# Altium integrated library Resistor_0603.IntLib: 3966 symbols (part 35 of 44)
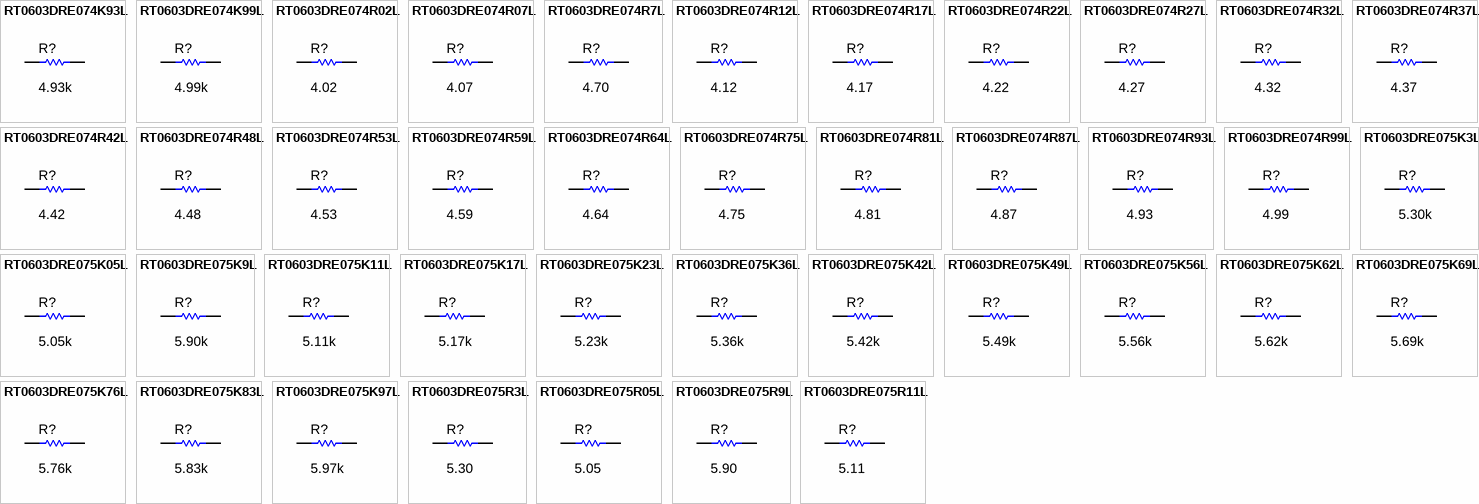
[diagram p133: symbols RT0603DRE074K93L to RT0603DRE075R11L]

## RT0603DRE075K23L
designator R?  ValueDisplayed: 5.23k  (hidden comment: RT0603DRE075K23L)
RES, 5.23 k, 0.5%, 0.1 W, 0603; Manufacturer: Yageo America; CompType: Resistor; Value: 5.23k; Res_ohm: 5230; Value_Code: 5k23; Tolerance_%: 0.5; Power_W: 0.1; Value2: 0.1W; VDC_V: 75; TempCo: 50 ppm/C; SizeArea_mm2: 1.28; SizeX_mm: 1.6; SizeY_mm: 0.8; SizeZ_mm: 1; EIA_Code: E192; U/M: EA; AEC Category: Q200; Green_Lifecycle: Active; Green_REACh: Passed
signal-integrity model Resistor
simulation model Resistor
footprint 0603
footprint 0603M
footprint 0603L
footprint 0603_HV
footprint 0603S
pins: 1, 2

## RT0603DRE075K36L
designator R?  ValueDisplayed: 5.36k  (hidden comment: RT0603DRE075K36L)
RES, 5.36 k, 0.5%, 0.1 W, 0603; Manufacturer: Yageo America; CompType: Resistor; Value: 5.36k; Res_ohm: 5360; Value_Code: 5k36; Tolerance_%: 0.5; Power_W: 0.1; Value2: 0.1W; VDC_V: 75; TempCo: 50 ppm/C; SizeArea_mm2: 1.28; SizeX_mm: 1.6; SizeY_mm: 0.8; SizeZ_mm: 1; EIA_Code: E192; U/M: EA; AEC Category: Q200
signal-integrity model Resistor
simulation model Resistor
footprint 0603
footprint 0603M
footprint 0603L
footprint 0603_HV
footprint 0603S
pins: 1, 2

## RT0603DRE075K42L
designator R?  ValueDisplayed: 5.42k  (hidden comment: RT0603DRE075K42L)
RES, 5.42 k, 0.5%, 0.1 W, 0603; Manufacturer: Yageo America; CompType: Resistor; Value: 5.42k; Res_ohm: 5420; Value_Code: 5k42; Tolerance_%: 0.5; Power_W: 0.1; Value2: 0.1W; VDC_V: 75; TempCo: 50 ppm/C; SizeArea_mm2: 1.28; SizeX_mm: 1.6; SizeY_mm: 0.8; SizeZ_mm: 1; EIA_Code: E192; U/M: EA; AEC Category: Q200
signal-integrity model Resistor
simulation model Resistor
footprint 0603
footprint 0603M
footprint 0603L
footprint 0603_HV
footprint 0603S
pins: 1, 2

## RT0603DRE075K49L
designator R?  ValueDisplayed: 5.49k  (hidden comment: RT0603DRE075K49L)
RES, 5.49 k, 0.5%, 0.1 W, 0603; Manufacturer: Yageo America; CompType: Resistor; Value: 5.49k; Res_ohm: 5490; Value_Code: 5k49; Tolerance_%: 0.5; Power_W: 0.1; Value2: 0.1W; VDC_V: 75; TempCo: 50 ppm/C; SizeArea_mm2: 1.28; SizeX_mm: 1.6; SizeY_mm: 0.8; SizeZ_mm: 1; EIA_Code: E192; U/M: EA; AEC Category: Q200
signal-integrity model Resistor
simulation model Resistor
footprint 0603
footprint 0603M
footprint 0603L
footprint 0603_HV
footprint 0603S
pins: 1, 2

## RT0603DRE075K56L
designator R?  ValueDisplayed: 5.56k  (hidden comment: RT0603DRE075K56L)
RES, 5.56 k, 0.5%, 0.1 W, 0603; Manufacturer: Yageo America; CompType: Resistor; Value: 5.56k; Res_ohm: 5560; Value_Code: 5k56; Tolerance_%: 0.5; Power_W: 0.1; Value2: 0.1W; VDC_V: 75; TempCo: 50 ppm/C; SizeArea_mm2: 1.28; SizeX_mm: 1.6; SizeY_mm: 0.8; SizeZ_mm: 1; EIA_Code: E192; U/M: EA; AEC Category: Q200
signal-integrity model Resistor
simulation model Resistor
footprint 0603
footprint 0603M
footprint 0603L
footprint 0603_HV
footprint 0603S
pins: 1, 2

## RT0603DRE075K62L
designator R?  ValueDisplayed: 5.62k  (hidden comment: RT0603DRE075K62L)
RES, 5.62 k, 0.5%, 0.1 W, 0603; Manufacturer: Yageo America; CompType: Resistor; Value: 5.62k; Res_ohm: 5620; Value_Code: 5k62; Tolerance_%: 0.5; Power_W: 0.1; Value2: 0.1W; VDC_V: 75; TempCo: 50 ppm/C; SizeArea_mm2: 1.28; SizeX_mm: 1.6; SizeY_mm: 0.8; SizeZ_mm: 1; EIA_Code: E192; U/M: EA; AEC Category: Q200
signal-integrity model Resistor
simulation model Resistor
footprint 0603
footprint 0603M
footprint 0603L
footprint 0603_HV
footprint 0603S
pins: 1, 2

## RT0603DRE075K69L
designator R?  ValueDisplayed: 5.69k  (hidden comment: RT0603DRE075K69L)
RES, 5.69 k, 0.5%, 0.1 W, 0603; Manufacturer: Yageo America; CompType: Resistor; Value: 5.69k; Res_ohm: 5690; Value_Code: 5k69; Tolerance_%: 0.5; Power_W: 0.1; Value2: 0.1W; VDC_V: 75; TempCo: 50 ppm/C; SizeArea_mm2: 1.28; SizeX_mm: 1.6; SizeY_mm: 0.8; SizeZ_mm: 1; EIA_Code: E192; U/M: EA; AEC Category: Q200
signal-integrity model Resistor
simulation model Resistor
footprint 0603
footprint 0603M
footprint 0603L
footprint 0603_HV
footprint 0603S
pins: 1, 2

## RT0603DRE075K76L
designator R?  ValueDisplayed: 5.76k  (hidden comment: RT0603DRE075K76L)
RES, 5.76 k, 0.5%, 0.1 W, 0603; Manufacturer: Yageo America; CompType: Resistor; Value: 5.76k; Res_ohm: 5760; Value_Code: 5k76; Tolerance_%: 0.5; Power_W: 0.1; Value2: 0.1W; VDC_V: 75; TempCo: 50 ppm/C; SizeArea_mm2: 1.28; SizeX_mm: 1.6; SizeY_mm: 0.8; SizeZ_mm: 1; EIA_Code: E192; U/M: EA; AEC Category: Q200
signal-integrity model Resistor
simulation model Resistor
footprint 0603
footprint 0603M
footprint 0603L
footprint 0603_HV
footprint 0603S
pins: 1, 2

## RT0603DRE075K83L
designator R?  ValueDisplayed: 5.83k  (hidden comment: RT0603DRE075K83L)
RES, 5.83 k, 0.5%, 0.1 W, 0603; Manufacturer: Yageo America; CompType: Resistor; Value: 5.83k; Res_ohm: 5830; Value_Code: 5k83; Tolerance_%: 0.5; Power_W: 0.1; Value2: 0.1W; VDC_V: 75; TempCo: 50 ppm/C; SizeArea_mm2: 1.28; SizeX_mm: 1.6; SizeY_mm: 0.8; SizeZ_mm: 1; EIA_Code: E192; U/M: EA; AEC Category: Q200
signal-integrity model Resistor
simulation model Resistor
footprint 0603
footprint 0603M
footprint 0603L
footprint 0603_HV
footprint 0603S
pins: 1, 2

## RT0603DRE075K97L
designator R?  ValueDisplayed: 5.97k  (hidden comment: RT0603DRE075K97L)
RES, 5.97 k, 0.5%, 0.1 W, 0603; Manufacturer: Yageo America; CompType: Resistor; Value: 5.97k; Res_ohm: 5970; Value_Code: 5k97; Tolerance_%: 0.5; Power_W: 0.1; Value2: 0.1W; VDC_V: 75; TempCo: 50 ppm/C; SizeArea_mm2: 1.28; SizeX_mm: 1.6; SizeY_mm: 0.8; SizeZ_mm: 1; EIA_Code: E192; U/M: EA; AEC Category: Q200
signal-integrity model Resistor
simulation model Resistor
footprint 0603
footprint 0603M
footprint 0603L
footprint 0603_HV
footprint 0603S
pins: 1, 2

## RT0603DRE075R3L
designator R?  ValueDisplayed: 5.30  (hidden comment: RT0603DRE075R3L)
RES, 5.30, 0.5%, 0.1 W, 0603; Manufacturer: Yageo America; CompType: Resistor; Value: 5.30; Res_ohm: 5.3; Value_Code: 5R30; Tolerance_%: 0.5; Power_W: 0.1; Value2: 0.1W; VDC_V: 75; TempCo: 50 ppm/C; SizeArea_mm2: 1.28; SizeX_mm: 1.6; SizeY_mm: 0.8; SizeZ_mm: 1; EIA_Code: E192; U/M: EA; AEC Category: Q200
signal-integrity model Resistor
simulation model Resistor
footprint 0603
footprint 0603M
footprint 0603L
footprint 0603_HV
footprint 0603S
pins: 1, 2

## RT0603DRE075R05L
designator R?  ValueDisplayed: 5.05  (hidden comment: RT0603DRE075R05L)
RES, 5.05, 0.5%, 0.1 W, 0603; Manufacturer: Yageo America; CompType: Resistor; Value: 5.05; Value_Code: 5R05; Tolerance_%: 0.5; Power_W: 0.1; Value2: 0.1W; VDC_V: 75; TempCo: 50 ppm/C; SizeArea_mm2: 1.28; SizeX_mm: 1.6; SizeY_mm: 0.8; SizeZ_mm: 1; EIA_Code: E192; U/M: EA; AEC Category: Q200
signal-integrity model Resistor
simulation model Resistor
footprint 0603
footprint 0603M
footprint 0603L
footprint 0603_HV
footprint 0603S
pins: 1, 2

## RT0603DRE075R9L
designator R?  ValueDisplayed: 5.90  (hidden comment: RT0603DRE075R9L)
RES, 5.90, 0.5%, 0.1 W, 0603; Manufacturer: Yageo America; CompType: Resistor; Value: 5.90; Res_ohm: 5.9; Value_Code: 5R90; Tolerance_%: 0.5; Power_W: 0.1; Value2: 0.1W; VDC_V: 75; TempCo: 50 ppm/C; SizeArea_mm2: 1.28; SizeX_mm: 1.6; SizeY_mm: 0.8; SizeZ_mm: 1; EIA_Code: E192; U/M: EA; AEC Category: Q200
signal-integrity model Resistor
simulation model Resistor
footprint 0603
footprint 0603M
footprint 0603L
footprint 0603_HV
footprint 0603S
pins: 1, 2

## RT0603DRE075R11L
designator R?  ValueDisplayed: 5.11  (hidden comment: RT0603DRE075R11L)
RES, 5.11, 0.5%, 0.1 W, 0603; Manufacturer: Yageo America; CompType: Resistor; Value: 5.11; Value_Code: 5R11; Tolerance_%: 0.5; Power_W: 0.1; Value2: 0.1W; VDC_V: 75; TempCo: 50 ppm/C; SizeArea_mm2: 1.28; SizeX_mm: 1.6; SizeY_mm: 0.8; SizeZ_mm: 1; EIA_Code: E192; U/M: EA; AEC Category: Q200
signal-integrity model Resistor
simulation model Resistor
footprint 0603
footprint 0603M
footprint 0603L
footprint 0603_HV
footprint 0603S
pins: 1, 2

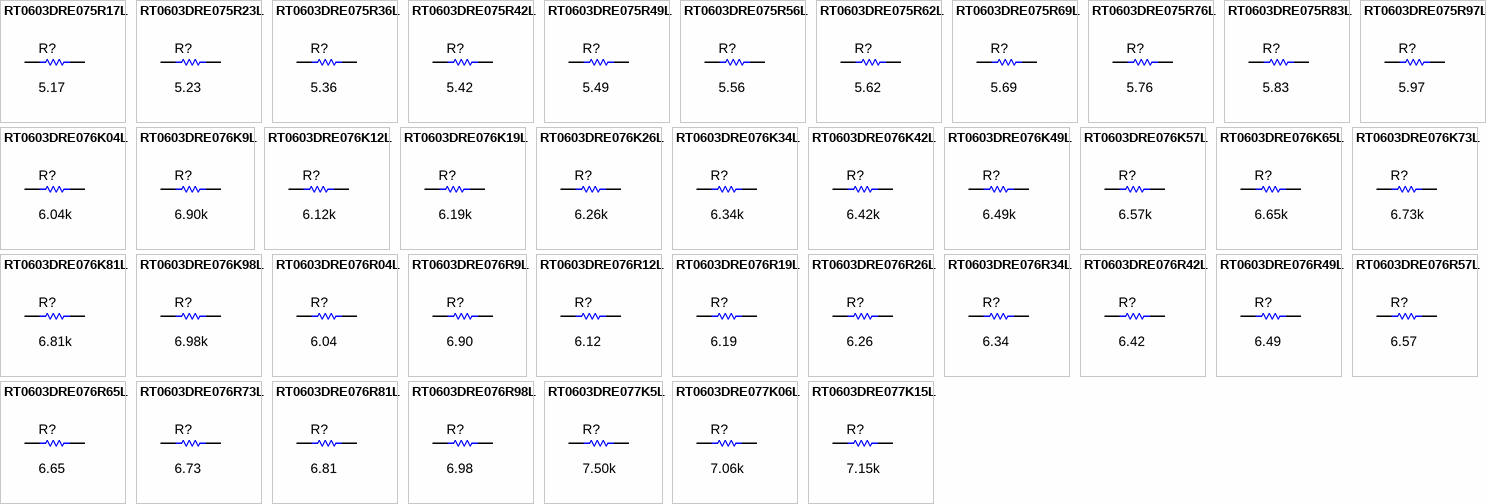
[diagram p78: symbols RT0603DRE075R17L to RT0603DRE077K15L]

## RT0603DRE075R17L
designator R?  ValueDisplayed: 5.17  (hidden comment: RT0603DRE075R17L)
RES, 5.17, 0.5%, 0.1 W, 0603; Manufacturer: Yageo America; CompType: Resistor; Value: 5.17; Value_Code: 5R17; Tolerance_%: 0.5; Power_W: 0.1; Value2: 0.1W; VDC_V: 75; TempCo: 50 ppm/C; SizeArea_mm2: 1.28; SizeX_mm: 1.6; SizeY_mm: 0.8; SizeZ_mm: 1; EIA_Code: E192; U/M: EA; AEC Category: Q200
signal-integrity model Resistor
simulation model Resistor
footprint 0603
footprint 0603M
footprint 0603L
footprint 0603_HV
footprint 0603S
pins: 1, 2

## RT0603DRE075R23L
designator R?  ValueDisplayed: 5.23  (hidden comment: RT0603DRE075R23L)
RES, 5.23, 0.5%, 0.1 W, 0603; Manufacturer: Yageo America; CompType: Resistor; Value: 5.23; Value_Code: 5R23; Tolerance_%: 0.5; Power_W: 0.1; Value2: 0.1W; VDC_V: 75; TempCo: 50 ppm/C; SizeArea_mm2: 1.28; SizeX_mm: 1.6; SizeY_mm: 0.8; SizeZ_mm: 1; EIA_Code: E192; U/M: EA; AEC Category: Q200
signal-integrity model Resistor
simulation model Resistor
footprint 0603
footprint 0603M
footprint 0603L
footprint 0603_HV
footprint 0603S
pins: 1, 2

## RT0603DRE075R36L
designator R?  ValueDisplayed: 5.36  (hidden comment: RT0603DRE075R36L)
RES, 5.36, 0.5%, 0.1 W, 0603; Manufacturer: Yageo America; CompType: Resistor; Value: 5.36; Value_Code: 5R36; Tolerance_%: 0.5; Power_W: 0.1; Value2: 0.1W; VDC_V: 75; TempCo: 50 ppm/C; SizeArea_mm2: 1.28; SizeX_mm: 1.6; SizeY_mm: 0.8; SizeZ_mm: 1; EIA_Code: E192; U/M: EA; AEC Category: Q200
signal-integrity model Resistor
simulation model Resistor
footprint 0603
footprint 0603M
footprint 0603L
footprint 0603_HV
footprint 0603S
pins: 1, 2

## RT0603DRE075R42L
designator R?  ValueDisplayed: 5.42  (hidden comment: RT0603DRE075R42L)
RES, 5.42, 0.5%, 0.1 W, 0603; Manufacturer: Yageo America; CompType: Resistor; Value: 5.42; Value_Code: 5R42; Tolerance_%: 0.5; Power_W: 0.1; Value2: 0.1W; VDC_V: 75; TempCo: 50 ppm/C; SizeArea_mm2: 1.28; SizeX_mm: 1.6; SizeY_mm: 0.8; SizeZ_mm: 1; EIA_Code: E192; U/M: EA; AEC Category: Q200
signal-integrity model Resistor
simulation model Resistor
footprint 0603
footprint 0603M
footprint 0603L
footprint 0603_HV
footprint 0603S
pins: 1, 2

## RT0603DRE075R49L
designator R?  ValueDisplayed: 5.49  (hidden comment: RT0603DRE075R49L)
RES, 5.49, 0.5%, 0.1 W, 0603; Manufacturer: Yageo America; CompType: Resistor; Value: 5.49; Value_Code: 5R49; Tolerance_%: 0.5; Power_W: 0.1; Value2: 0.1W; VDC_V: 75; TempCo: 50 ppm/C; SizeArea_mm2: 1.28; SizeX_mm: 1.6; SizeY_mm: 0.8; SizeZ_mm: 1; EIA_Code: E192; U/M: EA; AEC Category: Q200
signal-integrity model Resistor
simulation model Resistor
footprint 0603
footprint 0603M
footprint 0603L
footprint 0603_HV
footprint 0603S
pins: 1, 2

## RT0603DRE075R56L
designator R?  ValueDisplayed: 5.56  (hidden comment: RT0603DRE075R56L)
RES, 5.56, 0.5%, 0.1 W, 0603; Manufacturer: Yageo America; CompType: Resistor; Value: 5.56; Value_Code: 5R56; Tolerance_%: 0.5; Power_W: 0.1; Value2: 0.1W; VDC_V: 75; TempCo: 50 ppm/C; SizeArea_mm2: 1.28; SizeX_mm: 1.6; SizeY_mm: 0.8; SizeZ_mm: 1; EIA_Code: E192; U/M: EA; AEC Category: Q200
signal-integrity model Resistor
simulation model Resistor
footprint 0603
footprint 0603M
footprint 0603L
footprint 0603_HV
footprint 0603S
pins: 1, 2

## RT0603DRE075R62L
designator R?  ValueDisplayed: 5.62  (hidden comment: RT0603DRE075R62L)
RES, 5.62, 0.5%, 0.1 W, 0603; Manufacturer: Yageo America; CompType: Resistor; Value: 5.62; Value_Code: 5R62; Tolerance_%: 0.5; Power_W: 0.1; Value2: 0.1W; VDC_V: 75; TempCo: 50 ppm/C; SizeArea_mm2: 1.28; SizeX_mm: 1.6; SizeY_mm: 0.8; SizeZ_mm: 1; EIA_Code: E192; U/M: EA; AEC Category: Q200
signal-integrity model Resistor
simulation model Resistor
footprint 0603
footprint 0603M
footprint 0603L
footprint 0603_HV
footprint 0603S
pins: 1, 2

## RT0603DRE075R69L
designator R?  ValueDisplayed: 5.69  (hidden comment: RT0603DRE075R69L)
RES, 5.69, 0.5%, 0.1 W, 0603; Manufacturer: Yageo America; CompType: Resistor; Value: 5.69; Value_Code: 5R69; Tolerance_%: 0.5; Power_W: 0.1; Value2: 0.1W; VDC_V: 75; TempCo: 50 ppm/C; SizeArea_mm2: 1.28; SizeX_mm: 1.6; SizeY_mm: 0.8; SizeZ_mm: 1; EIA_Code: E192; U/M: EA; AEC Category: Q200
signal-integrity model Resistor
simulation model Resistor
footprint 0603
footprint 0603M
footprint 0603L
footprint 0603_HV
footprint 0603S
pins: 1, 2

## RT0603DRE075R76L
designator R?  ValueDisplayed: 5.76  (hidden comment: RT0603DRE075R76L)
RES, 5.76, 0.5%, 0.1 W, 0603; Manufacturer: Yageo America; CompType: Resistor; Value: 5.76; Value_Code: 5R76; Tolerance_%: 0.5; Power_W: 0.1; Value2: 0.1W; VDC_V: 75; TempCo: 50 ppm/C; SizeArea_mm2: 1.28; SizeX_mm: 1.6; SizeY_mm: 0.8; SizeZ_mm: 1; EIA_Code: E192; U/M: EA; AEC Category: Q200
signal-integrity model Resistor
simulation model Resistor
footprint 0603
footprint 0603M
footprint 0603L
footprint 0603_HV
footprint 0603S
pins: 1, 2

## RT0603DRE075R83L
designator R?  ValueDisplayed: 5.83  (hidden comment: RT0603DRE075R83L)
RES, 5.83, 0.5%, 0.1 W, 0603; Manufacturer: Yageo America; CompType: Resistor; Value: 5.83; Value_Code: 5R83; Tolerance_%: 0.5; Power_W: 0.1; Value2: 0.1W; VDC_V: 75; TempCo: 50 ppm/C; SizeArea_mm2: 1.28; SizeX_mm: 1.6; SizeY_mm: 0.8; SizeZ_mm: 1; EIA_Code: E192; U/M: EA; AEC Category: Q200
signal-integrity model Resistor
simulation model Resistor
footprint 0603
footprint 0603M
footprint 0603L
footprint 0603_HV
footprint 0603S
pins: 1, 2

## RT0603DRE075R97L
designator R?  ValueDisplayed: 5.97  (hidden comment: RT0603DRE075R97L)
RES, 5.97, 0.5%, 0.1 W, 0603; Manufacturer: Yageo America; CompType: Resistor; Value: 5.97; Value_Code: 5R97; Tolerance_%: 0.5; Power_W: 0.1; Value2: 0.1W; VDC_V: 75; TempCo: 50 ppm/C; SizeArea_mm2: 1.28; SizeX_mm: 1.6; SizeY_mm: 0.8; SizeZ_mm: 1; EIA_Code: E192; U/M: EA; AEC Category: Q200
signal-integrity model Resistor
simulation model Resistor
footprint 0603
footprint 0603M
footprint 0603L
footprint 0603_HV
footprint 0603S
pins: 1, 2

## RT0603DRE076K04L
designator R?  ValueDisplayed: 6.04k  (hidden comment: RT0603DRE076K04L)
RES, 6.04 k, 0.5%, 0.1 W, 0603; Manufacturer: Yageo America; CompType: Resistor; Value: 6.04k; Res_ohm: 6040; Value_Code: 6k04; Tolerance_%: 0.5; Power_W: 0.1; Value2: 0.1W; VDC_V: 75; TempCo: 50 ppm/C; SizeArea_mm2: 1.28; SizeX_mm: 1.6; SizeY_mm: 0.8; SizeZ_mm: 1; EIA_Code: E192; U/M: EA; AEC Category: Q200
signal-integrity model Resistor
simulation model Resistor
footprint 0603
footprint 0603M
footprint 0603L
footprint 0603_HV
footprint 0603S
pins: 1, 2

## RT0603DRE076K9L
designator R?  ValueDisplayed: 6.90k  (hidden comment: RT0603DRE076K9L)
RES, 6.90 k, 0.5%, 0.1 W, 0603; Manufacturer: Yageo America; CompType: Resistor; Value: 6.90k; Res_ohm: 6900; Value_Code: 6k90; Tolerance_%: 0.5; Power_W: 0.1; Value2: 0.1W; VDC_V: 75; TempCo: 50 ppm/C; SizeArea_mm2: 1.28; SizeX_mm: 1.6; SizeY_mm: 0.8; SizeZ_mm: 1; EIA_Code: E192; U/M: EA; AEC Category: Q200
signal-integrity model Resistor
simulation model Resistor
footprint 0603
footprint 0603M
footprint 0603L
footprint 0603_HV
footprint 0603S
pins: 1, 2

## RT0603DRE076K12L
designator R?  ValueDisplayed: 6.12k  (hidden comment: RT0603DRE076K12L)
RES, 6.12 k, 0.5%, 0.1 W, 0603; Manufacturer: Yageo America; CompType: Resistor; Value: 6.12k; Res_ohm: 6120; Value_Code: 6k12; Tolerance_%: 0.5; Power_W: 0.1; Value2: 0.1W; VDC_V: 75; TempCo: 50 ppm/C; SizeArea_mm2: 1.28; SizeX_mm: 1.6; SizeY_mm: 0.8; SizeZ_mm: 1; EIA_Code: E192; U/M: EA; AEC Category: Q200
signal-integrity model Resistor
simulation model Resistor
footprint 0603
footprint 0603M
footprint 0603L
footprint 0603_HV
footprint 0603S
pins: 1, 2

## RT0603DRE076K19L
designator R?  ValueDisplayed: 6.19k  (hidden comment: RT0603DRE076K19L)
RES, 6.19 k, 0.5%, 0.1 W, 0603; Manufacturer: Yageo America; CompType: Resistor; Value: 6.19k; Res_ohm: 6190; Value_Code: 6k19; Tolerance_%: 0.5; Power_W: 0.1; Value2: 0.1W; VDC_V: 75; TempCo: 50 ppm/C; SizeArea_mm2: 1.28; SizeX_mm: 1.6; SizeY_mm: 0.8; SizeZ_mm: 1; EIA_Code: E192; U/M: EA; AEC Category: Q200
signal-integrity model Resistor
simulation model Resistor
footprint 0603
footprint 0603M
footprint 0603L
footprint 0603_HV
footprint 0603S
pins: 1, 2

## RT0603DRE076K26L
designator R?  ValueDisplayed: 6.26k  (hidden comment: RT0603DRE076K26L)
RES, 6.26 k, 0.5%, 0.1 W, 0603; Manufacturer: Yageo America; CompType: Resistor; Value: 6.26k; Res_ohm: 6260; Value_Code: 6k26; Tolerance_%: 0.5; Power_W: 0.1; Value2: 0.1W; VDC_V: 75; TempCo: 50 ppm/C; SizeArea_mm2: 1.28; SizeX_mm: 1.6; SizeY_mm: 0.8; SizeZ_mm: 1; EIA_Code: E192; U/M: EA; AEC Category: Q200
signal-integrity model Resistor
simulation model Resistor
footprint 0603
footprint 0603M
footprint 0603L
footprint 0603_HV
footprint 0603S
pins: 1, 2

## RT0603DRE076K34L
designator R?  ValueDisplayed: 6.34k  (hidden comment: RT0603DRE076K34L)
RES, 6.34 k, 0.5%, 0.1 W, 0603; Manufacturer: Yageo America; CompType: Resistor; Value: 6.34k; Res_ohm: 6340; Value_Code: 6k34; Tolerance_%: 0.5; Power_W: 0.1; Value2: 0.1W; VDC_V: 75; TempCo: 50 ppm/C; SizeArea_mm2: 1.28; SizeX_mm: 1.6; SizeY_mm: 0.8; SizeZ_mm: 1; EIA_Code: E192; U/M: EA; AEC Category: Q200
signal-integrity model Resistor
simulation model Resistor
footprint 0603
footprint 0603M
footprint 0603L
footprint 0603_HV
footprint 0603S
pins: 1, 2

## RT0603DRE076K42L
designator R?  ValueDisplayed: 6.42k  (hidden comment: RT0603DRE076K42L)
RES, 6.42 k, 0.5%, 0.1 W, 0603; Manufacturer: Yageo America; CompType: Resistor; Value: 6.42k; Res_ohm: 6420; Value_Code: 6k42; Tolerance_%: 0.5; Power_W: 0.1; Value2: 0.1W; VDC_V: 75; TempCo: 50 ppm/C; SizeArea_mm2: 1.28; SizeX_mm: 1.6; SizeY_mm: 0.8; SizeZ_mm: 1; EIA_Code: E192; U/M: EA; AEC Category: Q200
signal-integrity model Resistor
simulation model Resistor
footprint 0603
footprint 0603M
footprint 0603L
footprint 0603_HV
footprint 0603S
pins: 1, 2

## RT0603DRE076K49L
designator R?  ValueDisplayed: 6.49k  (hidden comment: RT0603DRE076K49L)
RES, 6.49 k, 0.5%, 0.1 W, 0603; Manufacturer: Yageo America; CompType: Resistor; Value: 6.49k; Res_ohm: 6490; Value_Code: 6k49; Tolerance_%: 0.5; Power_W: 0.1; Value2: 0.1W; VDC_V: 75; TempCo: 50 ppm/C; SizeArea_mm2: 1.28; SizeX_mm: 1.6; SizeY_mm: 0.8; SizeZ_mm: 1; EIA_Code: E192; U/M: EA; AEC Category: Q200
signal-integrity model Resistor
simulation model Resistor
footprint 0603
footprint 0603M
footprint 0603L
footprint 0603_HV
footprint 0603S
pins: 1, 2

## RT0603DRE076K57L
designator R?  ValueDisplayed: 6.57k  (hidden comment: RT0603DRE076K57L)
RES, 6.57 k, 0.5%, 0.1 W, 0603; Manufacturer: Yageo America; CompType: Resistor; Value: 6.57k; Res_ohm: 6570; Value_Code: 6k57; Tolerance_%: 0.5; Power_W: 0.1; Value2: 0.1W; VDC_V: 75; TempCo: 50 ppm/C; SizeArea_mm2: 1.28; SizeX_mm: 1.6; SizeY_mm: 0.8; SizeZ_mm: 1; EIA_Code: E192; U/M: EA; AEC Category: Q200
signal-integrity model Resistor
simulation model Resistor
footprint 0603
footprint 0603M
footprint 0603L
footprint 0603_HV
footprint 0603S
pins: 1, 2

## RT0603DRE076K65L
designator R?  ValueDisplayed: 6.65k  (hidden comment: RT0603DRE076K65L)
RES, 6.65 k, 0.5%, 0.1 W, 0603; Manufacturer: Yageo America; CompType: Resistor; Value: 6.65k; Res_ohm: 6650; Value_Code: 6k65; Tolerance_%: 0.5; Power_W: 0.1; Value2: 0.1W; VDC_V: 75; TempCo: 50 ppm/C; SizeArea_mm2: 1.28; SizeX_mm: 1.6; SizeY_mm: 0.8; SizeZ_mm: 1; EIA_Code: E192; U/M: EA; AEC Category: Q200
signal-integrity model Resistor
simulation model Resistor
footprint 0603
footprint 0603M
footprint 0603L
footprint 0603_HV
footprint 0603S
pins: 1, 2

## RT0603DRE076K73L
designator R?  ValueDisplayed: 6.73k  (hidden comment: RT0603DRE076K73L)
RES, 6.73 k, 0.5%, 0.1 W, 0603; Manufacturer: Yageo America; CompType: Resistor; Value: 6.73k; Res_ohm: 6730; Value_Code: 6k73; Tolerance_%: 0.5; Power_W: 0.1; Value2: 0.1W; VDC_V: 75; TempCo: 50 ppm/C; SizeArea_mm2: 1.28; SizeX_mm: 1.6; SizeY_mm: 0.8; SizeZ_mm: 1; EIA_Code: E192; U/M: EA; AEC Category: Q200
signal-integrity model Resistor
simulation model Resistor
footprint 0603
footprint 0603M
footprint 0603L
footprint 0603_HV
footprint 0603S
pins: 1, 2

## RT0603DRE076K81L
designator R?  ValueDisplayed: 6.81k  (hidden comment: RT0603DRE076K81L)
RES, 6.81 k, 0.5%, 0.1 W, 0603; Manufacturer: Yageo America; CompType: Resistor; Value: 6.81k; Res_ohm: 6810; Value_Code: 6k81; Tolerance_%: 0.5; Power_W: 0.1; Value2: 0.1W; VDC_V: 75; TempCo: 50 ppm/C; SizeArea_mm2: 1.28; SizeX_mm: 1.6; SizeY_mm: 0.8; SizeZ_mm: 1; EIA_Code: E192; U/M: EA; AEC Category: Q200
signal-integrity model Resistor
simulation model Resistor
footprint 0603
footprint 0603M
footprint 0603L
footprint 0603_HV
footprint 0603S
pins: 1, 2

## RT0603DRE076K98L
designator R?  ValueDisplayed: 6.98k  (hidden comment: RT0603DRE076K98L)
RES, 6.98 k, 0.5%, 0.1 W, 0603; Manufacturer: Yageo America; CompType: Resistor; Value: 6.98k; Res_ohm: 6980; Value_Code: 6k98; Tolerance_%: 0.5; Power_W: 0.1; Value2: 0.1W; VDC_V: 75; TempCo: 50 ppm/C; SizeArea_mm2: 1.28; SizeX_mm: 1.6; SizeY_mm: 0.8; SizeZ_mm: 1; EIA_Code: E192; U/M: EA; AEC Category: Q200
signal-integrity model Resistor
simulation model Resistor
footprint 0603
footprint 0603M
footprint 0603L
footprint 0603_HV
footprint 0603S
pins: 1, 2

## RT0603DRE076R04L
designator R?  ValueDisplayed: 6.04  (hidden comment: RT0603DRE076R04L)
RES, 6.04, 0.5%, 0.1 W, 0603; Manufacturer: Yageo America; CompType: Resistor; Value: 6.04; Value_Code: 6R04; Tolerance_%: 0.5; Power_W: 0.1; Value2: 0.1W; VDC_V: 75; TempCo: 50 ppm/C; SizeArea_mm2: 1.28; SizeX_mm: 1.6; SizeY_mm: 0.8; SizeZ_mm: 1; EIA_Code: E192; U/M: EA; AEC Category: Q200
signal-integrity model Resistor
simulation model Resistor
footprint 0603
footprint 0603M
footprint 0603L
footprint 0603_HV
footprint 0603S
pins: 1, 2

## RT0603DRE076R9L
designator R?  ValueDisplayed: 6.90  (hidden comment: RT0603DRE076R9L)
RES, 6.90, 0.5%, 0.1 W, 0603; Manufacturer: Yageo America; CompType: Resistor; Value: 6.90; Res_ohm: 6.9; Value_Code: 6R90; Tolerance_%: 0.5; Power_W: 0.1; Value2: 0.1W; VDC_V: 75; TempCo: 50 ppm/C; SizeArea_mm2: 1.28; SizeX_mm: 1.6; SizeY_mm: 0.8; SizeZ_mm: 1; EIA_Code: E192; U/M: EA; AEC Category: Q200
signal-integrity model Resistor
simulation model Resistor
footprint 0603
footprint 0603M
footprint 0603L
footprint 0603_HV
footprint 0603S
pins: 1, 2

## RT0603DRE076R12L
designator R?  ValueDisplayed: 6.12  (hidden comment: RT0603DRE076R12L)
RES, 6.12, 0.5%, 0.1 W, 0603; Manufacturer: Yageo America; CompType: Resistor; Value: 6.12; Value_Code: 6R12; Tolerance_%: 0.5; Power_W: 0.1; Value2: 0.1W; VDC_V: 75; TempCo: 50 ppm/C; SizeArea_mm2: 1.28; SizeX_mm: 1.6; SizeY_mm: 0.8; SizeZ_mm: 1; EIA_Code: E192; U/M: EA; AEC Category: Q200
signal-integrity model Resistor
simulation model Resistor
footprint 0603
footprint 0603M
footprint 0603L
footprint 0603_HV
footprint 0603S
pins: 1, 2

## RT0603DRE076R19L
designator R?  ValueDisplayed: 6.19  (hidden comment: RT0603DRE076R19L)
RES, 6.19, 0.5%, 0.1 W, 0603; Manufacturer: Yageo America; CompType: Resistor; Value: 6.19; Value_Code: 6R19; Tolerance_%: 0.5; Power_W: 0.1; Value2: 0.1W; VDC_V: 75; TempCo: 50 ppm/C; SizeArea_mm2: 1.28; SizeX_mm: 1.6; SizeY_mm: 0.8; SizeZ_mm: 1; EIA_Code: E192; U/M: EA; AEC Category: Q200
signal-integrity model Resistor
simulation model Resistor
footprint 0603
footprint 0603M
footprint 0603L
footprint 0603_HV
footprint 0603S
pins: 1, 2

## RT0603DRE076R26L
designator R?  ValueDisplayed: 6.26  (hidden comment: RT0603DRE076R26L)
RES, 6.26, 0.5%, 0.1 W, 0603; Manufacturer: Yageo America; CompType: Resistor; Value: 6.26; Value_Code: 6R26; Tolerance_%: 0.5; Power_W: 0.1; Value2: 0.1W; VDC_V: 75; TempCo: 50 ppm/C; SizeArea_mm2: 1.28; SizeX_mm: 1.6; SizeY_mm: 0.8; SizeZ_mm: 1; EIA_Code: E192; U/M: EA; AEC Category: Q200
signal-integrity model Resistor
simulation model Resistor
footprint 0603
footprint 0603M
footprint 0603L
footprint 0603_HV
footprint 0603S
pins: 1, 2

## RT0603DRE076R34L
designator R?  ValueDisplayed: 6.34  (hidden comment: RT0603DRE076R34L)
RES, 6.34, 0.5%, 0.1 W, 0603; Manufacturer: Yageo America; CompType: Resistor; Value: 6.34; Value_Code: 6R34; Tolerance_%: 0.5; Power_W: 0.1; Value2: 0.1W; VDC_V: 75; TempCo: 50 ppm/C; SizeArea_mm2: 1.28; SizeX_mm: 1.6; SizeY_mm: 0.8; SizeZ_mm: 1; EIA_Code: E192; U/M: EA; AEC Category: Q200
signal-integrity model Resistor
simulation model Resistor
footprint 0603
footprint 0603M
footprint 0603L
footprint 0603_HV
footprint 0603S
pins: 1, 2

## RT0603DRE076R42L
designator R?  ValueDisplayed: 6.42  (hidden comment: RT0603DRE076R42L)
RES, 6.42, 0.5%, 0.1 W, 0603; Manufacturer: Yageo America; CompType: Resistor; Value: 6.42; Value_Code: 6R42; Tolerance_%: 0.5; Power_W: 0.1; Value2: 0.1W; VDC_V: 75; TempCo: 50 ppm/C; SizeArea_mm2: 1.28; SizeX_mm: 1.6; SizeY_mm: 0.8; SizeZ_mm: 1; EIA_Code: E192; U/M: EA; AEC Category: Q200
signal-integrity model Resistor
simulation model Resistor
footprint 0603
footprint 0603M
footprint 0603L
footprint 0603_HV
footprint 0603S
pins: 1, 2

## RT0603DRE076R49L
designator R?  ValueDisplayed: 6.49  (hidden comment: RT0603DRE076R49L)
RES, 6.49, 0.5%, 0.1 W, 0603; Manufacturer: Yageo America; CompType: Resistor; Value: 6.49; Value_Code: 6R49; Tolerance_%: 0.5; Power_W: 0.1; Value2: 0.1W; VDC_V: 75; TempCo: 50 ppm/C; SizeArea_mm2: 1.28; SizeX_mm: 1.6; SizeY_mm: 0.8; SizeZ_mm: 1; EIA_Code: E192; U/M: EA; AEC Category: Q200
signal-integrity model Resistor
simulation model Resistor
footprint 0603
footprint 0603M
footprint 0603L
footprint 0603_HV
footprint 0603S
pins: 1, 2

## RT0603DRE076R57L
designator R?  ValueDisplayed: 6.57  (hidden comment: RT0603DRE076R57L)
RES, 6.57, 0.5%, 0.1 W, 0603; Manufacturer: Yageo America; CompType: Resistor; Value: 6.57; Value_Code: 6R57; Tolerance_%: 0.5; Power_W: 0.1; Value2: 0.1W; VDC_V: 75; TempCo: 50 ppm/C; SizeArea_mm2: 1.28; SizeX_mm: 1.6; SizeY_mm: 0.8; SizeZ_mm: 1; EIA_Code: E192; U/M: EA; AEC Category: Q200
signal-integrity model Resistor
simulation model Resistor
footprint 0603
footprint 0603M
footprint 0603L
footprint 0603_HV
footprint 0603S
pins: 1, 2

## RT0603DRE076R65L
designator R?  ValueDisplayed: 6.65  (hidden comment: RT0603DRE076R65L)
RES, 6.65, 0.5%, 0.1 W, 0603; Manufacturer: Yageo America; CompType: Resistor; Value: 6.65; Value_Code: 6R65; Tolerance_%: 0.5; Power_W: 0.1; Value2: 0.1W; VDC_V: 75; TempCo: 50 ppm/C; SizeArea_mm2: 1.28; SizeX_mm: 1.6; SizeY_mm: 0.8; SizeZ_mm: 1; EIA_Code: E192; U/M: EA; AEC Category: Q200
signal-integrity model Resistor
simulation model Resistor
footprint 0603
footprint 0603M
footprint 0603L
footprint 0603_HV
footprint 0603S
pins: 1, 2

## RT0603DRE076R73L
designator R?  ValueDisplayed: 6.73  (hidden comment: RT0603DRE076R73L)
RES, 6.73, 0.5%, 0.1 W, 0603; Manufacturer: Yageo America; CompType: Resistor; Value: 6.73; Value_Code: 6R73; Tolerance_%: 0.5; Power_W: 0.1; Value2: 0.1W; VDC_V: 75; TempCo: 50 ppm/C; SizeArea_mm2: 1.28; SizeX_mm: 1.6; SizeY_mm: 0.8; SizeZ_mm: 1; EIA_Code: E192; U/M: EA; AEC Category: Q200
signal-integrity model Resistor
simulation model Resistor
footprint 0603
footprint 0603M
footprint 0603L
footprint 0603_HV
footprint 0603S
pins: 1, 2

## RT0603DRE076R81L
designator R?  ValueDisplayed: 6.81  (hidden comment: RT0603DRE076R81L)
RES, 6.81, 0.5%, 0.1 W, 0603; Manufacturer: Yageo America; CompType: Resistor; Value: 6.81; Value_Code: 6R81; Tolerance_%: 0.5; Power_W: 0.1; Value2: 0.1W; VDC_V: 75; TempCo: 50 ppm/C; SizeArea_mm2: 1.28; SizeX_mm: 1.6; SizeY_mm: 0.8; SizeZ_mm: 1; EIA_Code: E192; U/M: EA; AEC Category: Q200
signal-integrity model Resistor
simulation model Resistor
footprint 0603
footprint 0603M
footprint 0603L
footprint 0603_HV
footprint 0603S
pins: 1, 2

## RT0603DRE076R98L
designator R?  ValueDisplayed: 6.98  (hidden comment: RT0603DRE076R98L)
RES, 6.98, 0.5%, 0.1 W, 0603; Manufacturer: Yageo America; CompType: Resistor; Value: 6.98; Value_Code: 6R98; Tolerance_%: 0.5; Power_W: 0.1; Value2: 0.1W; VDC_V: 75; TempCo: 50 ppm/C; SizeArea_mm2: 1.28; SizeX_mm: 1.6; SizeY_mm: 0.8; SizeZ_mm: 1; EIA_Code: E192; U/M: EA; AEC Category: Q200
signal-integrity model Resistor
simulation model Resistor
footprint 0603
footprint 0603M
footprint 0603L
footprint 0603_HV
footprint 0603S
pins: 1, 2

## RT0603DRE077K5L
designator R?  ValueDisplayed: 7.50k  (hidden comment: RT0603DRE077K5L)
RES, 7.50 k, 0.5%, 0.1 W, 0603; Manufacturer: Yageo America; CompType: Resistor; Value: 7.50k; Res_ohm: 7500; Value_Code: 7k50; Tolerance_%: 0.5; Power_W: 0.1; Value2: 0.1W; VDC_V: 75; TempCo: 50 ppm/C; SizeArea_mm2: 1.28; SizeX_mm: 1.6; SizeY_mm: 0.8; SizeZ_mm: 1; EIA_Code: E192; U/M: EA; AEC Category: Q200
signal-integrity model Resistor
simulation model Resistor
footprint 0603
footprint 0603M
footprint 0603L
footprint 0603_HV
footprint 0603S
pins: 1, 2

## RT0603DRE077K06L
designator R?  ValueDisplayed: 7.06k  (hidden comment: RT0603DRE077K06L)
RES, 7.06 k, 0.5%, 0.1 W, 0603; Manufacturer: Yageo America; CompType: Resistor; Value: 7.06k; Res_ohm: 7060; Value_Code: 7k06; Tolerance_%: 0.5; Power_W: 0.1; Value2: 0.1W; VDC_V: 75; TempCo: 50 ppm/C; SizeArea_mm2: 1.28; SizeX_mm: 1.6; SizeY_mm: 0.8; SizeZ_mm: 1; EIA_Code: E192; U/M: EA; AEC Category: Q200
signal-integrity model Resistor
simulation model Resistor
footprint 0603
footprint 0603M
footprint 0603L
footprint 0603_HV
footprint 0603S
pins: 1, 2

## RT0603DRE077K15L
designator R?  ValueDisplayed: 7.15k  (hidden comment: RT0603DRE077K15L)
RES, 7.15 k, 0.5%, 0.1 W, 0603; Manufacturer: Yageo America; CompType: Resistor; Value: 7.15k; Res_ohm: 7150; Value_Code: 7k15; Tolerance_%: 0.5; Power_W: 0.1; Value2: 0.1W; VDC_V: 75; TempCo: 50 ppm/C; SizeArea_mm2: 1.28; SizeX_mm: 1.6; SizeY_mm: 0.8; SizeZ_mm: 1; EIA_Code: E192; U/M: EA; AEC Category: Q200
signal-integrity model Resistor
simulation model Resistor
footprint 0603
footprint 0603M
footprint 0603L
footprint 0603_HV
footprint 0603S
pins: 1, 2

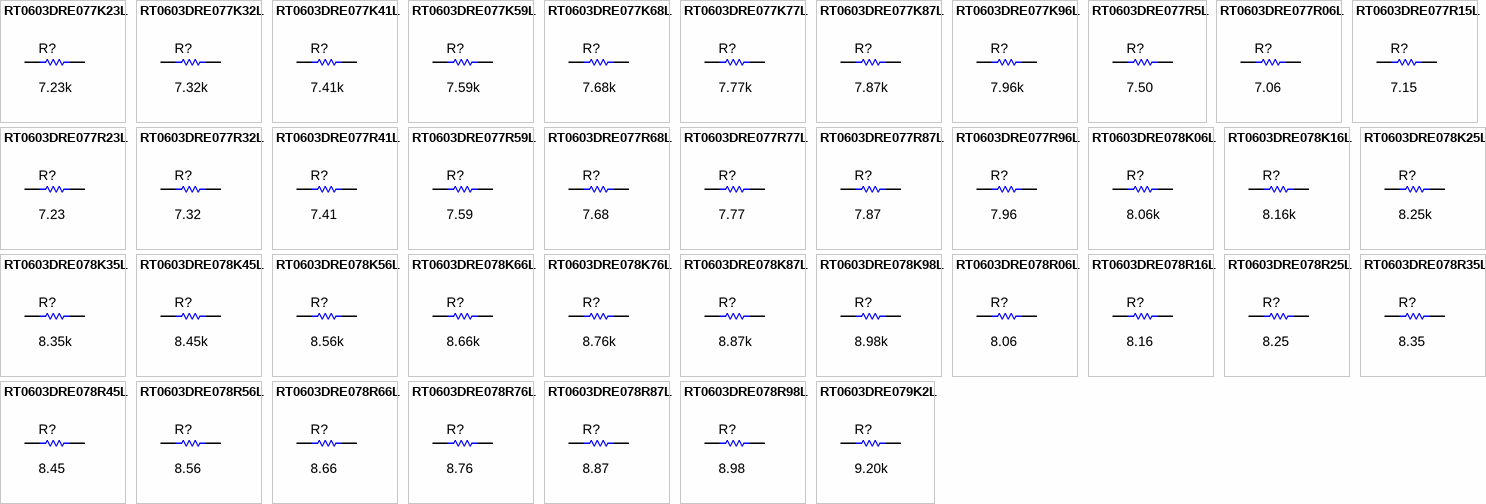
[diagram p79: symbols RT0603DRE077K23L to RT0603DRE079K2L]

## RT0603DRE077K23L
designator R?  ValueDisplayed: 7.23k  (hidden comment: RT0603DRE077K23L)
RES, 7.23 k, 0.5%, 0.1 W, 0603; Manufacturer: Yageo America; CompType: Resistor; Value: 7.23k; Res_ohm: 7230; Value_Code: 7k23; Tolerance_%: 0.5; Power_W: 0.1; Value2: 0.1W; VDC_V: 75; TempCo: 50 ppm/C; SizeArea_mm2: 1.28; SizeX_mm: 1.6; SizeY_mm: 0.8; SizeZ_mm: 1; EIA_Code: E192; U/M: EA; AEC Category: Q200
signal-integrity model Resistor
simulation model Resistor
footprint 0603
footprint 0603M
footprint 0603L
footprint 0603_HV
footprint 0603S
pins: 1, 2

## RT0603DRE077K32L
designator R?  ValueDisplayed: 7.32k  (hidden comment: RT0603DRE077K32L)
RES, 7.32 k, 0.5%, 0.1 W, 0603; Manufacturer: Yageo America; CompType: Resistor; Value: 7.32k; Res_ohm: 7320; Value_Code: 7k32; Tolerance_%: 0.5; Power_W: 0.1; Value2: 0.1W; VDC_V: 75; TempCo: 50 ppm/C; SizeArea_mm2: 1.28; SizeX_mm: 1.6; SizeY_mm: 0.8; SizeZ_mm: 1; EIA_Code: E192; U/M: EA; AEC Category: Q200
signal-integrity model Resistor
simulation model Resistor
footprint 0603
footprint 0603M
footprint 0603L
footprint 0603_HV
footprint 0603S
pins: 1, 2

## RT0603DRE077K41L
designator R?  ValueDisplayed: 7.41k  (hidden comment: RT0603DRE077K41L)
RES, 7.41 k, 0.5%, 0.1 W, 0603; Manufacturer: Yageo America; CompType: Resistor; Value: 7.41k; Res_ohm: 7410; Value_Code: 7k41; Tolerance_%: 0.5; Power_W: 0.1; Value2: 0.1W; VDC_V: 75; TempCo: 50 ppm/C; SizeArea_mm2: 1.28; SizeX_mm: 1.6; SizeY_mm: 0.8; SizeZ_mm: 1; EIA_Code: E192; U/M: EA; AEC Category: Q200
signal-integrity model Resistor
simulation model Resistor
footprint 0603
footprint 0603M
footprint 0603L
footprint 0603_HV
footprint 0603S
pins: 1, 2

## RT0603DRE077K59L
designator R?  ValueDisplayed: 7.59k  (hidden comment: RT0603DRE077K59L)
RES, 7.59 k, 0.5%, 0.1 W, 0603; Manufacturer: Yageo America; CompType: Resistor; Value: 7.59k; Res_ohm: 7590; Value_Code: 7k59; Tolerance_%: 0.5; Power_W: 0.1; Value2: 0.1W; VDC_V: 75; TempCo: 50 ppm/C; SizeArea_mm2: 1.28; SizeX_mm: 1.6; SizeY_mm: 0.8; SizeZ_mm: 1; EIA_Code: E192; U/M: EA; AEC Category: Q200
signal-integrity model Resistor
simulation model Resistor
footprint 0603
footprint 0603M
footprint 0603L
footprint 0603_HV
footprint 0603S
pins: 1, 2

## RT0603DRE077K68L
designator R?  ValueDisplayed: 7.68k  (hidden comment: RT0603DRE077K68L)
RES, 7.68 k, 0.5%, 0.1 W, 0603; Manufacturer: Yageo America; CompType: Resistor; Value: 7.68k; Res_ohm: 7680; Value_Code: 7k68; Tolerance_%: 0.5; Power_W: 0.1; Value2: 0.1W; VDC_V: 75; TempCo: 50 ppm/C; SizeArea_mm2: 1.28; SizeX_mm: 1.6; SizeY_mm: 0.8; SizeZ_mm: 1; EIA_Code: E192; U/M: EA; AEC Category: Q200; Green_Lifecycle: Active; Green_REACh: Passed
signal-integrity model Resistor
simulation model Resistor
footprint 0603
footprint 0603M
footprint 0603L
footprint 0603_HV
footprint 0603S
pins: 1, 2

## RT0603DRE077K77L
designator R?  ValueDisplayed: 7.77k  (hidden comment: RT0603DRE077K77L)
RES, 7.77 k, 0.5%, 0.1 W, 0603; Manufacturer: Yageo America; CompType: Resistor; Value: 7.77k; Res_ohm: 7770; Value_Code: 7k77; Tolerance_%: 0.5; Power_W: 0.1; Value2: 0.1W; VDC_V: 75; TempCo: 50 ppm/C; SizeArea_mm2: 1.28; SizeX_mm: 1.6; SizeY_mm: 0.8; SizeZ_mm: 1; EIA_Code: E192; U/M: EA; AEC Category: Q200
signal-integrity model Resistor
simulation model Resistor
footprint 0603
footprint 0603M
footprint 0603L
footprint 0603_HV
footprint 0603S
pins: 1, 2

## RT0603DRE077K87L
designator R?  ValueDisplayed: 7.87k  (hidden comment: RT0603DRE077K87L)
RES, 7.87 k, 0.5%, 0.1 W, 0603; Manufacturer: Yageo America; CompType: Resistor; Value: 7.87k; Res_ohm: 7870; Value_Code: 7k87; Tolerance_%: 0.5; Power_W: 0.1; Value2: 0.1W; VDC_V: 75; TempCo: 50 ppm/C; SizeArea_mm2: 1.28; SizeX_mm: 1.6; SizeY_mm: 0.8; SizeZ_mm: 1; EIA_Code: E192; U/M: EA; AEC Category: Q200
signal-integrity model Resistor
simulation model Resistor
footprint 0603
footprint 0603M
footprint 0603L
footprint 0603_HV
footprint 0603S
pins: 1, 2

## RT0603DRE077K96L
designator R?  ValueDisplayed: 7.96k  (hidden comment: RT0603DRE077K96L)
RES, 7.96 k, 0.5%, 0.1 W, 0603; Manufacturer: Yageo America; CompType: Resistor; Value: 7.96k; Res_ohm: 7960; Value_Code: 7k96; Tolerance_%: 0.5; Power_W: 0.1; Value2: 0.1W; VDC_V: 75; TempCo: 50 ppm/C; SizeArea_mm2: 1.28; SizeX_mm: 1.6; SizeY_mm: 0.8; SizeZ_mm: 1; EIA_Code: E192; U/M: EA; AEC Category: Q200
signal-integrity model Resistor
simulation model Resistor
footprint 0603
footprint 0603M
footprint 0603L
footprint 0603_HV
footprint 0603S
pins: 1, 2

## RT0603DRE077R5L
designator R?  ValueDisplayed: 7.50  (hidden comment: RT0603DRE077R5L)
RES, 7.50, 0.5%, 0.1 W, 0603; Manufacturer: Yageo America; CompType: Resistor; Value: 7.50; Res_ohm: 7.5; Value_Code: 7R50; Tolerance_%: 0.5; Power_W: 0.1; Value2: 0.1W; VDC_V: 75; TempCo: 50 ppm/C; SizeArea_mm2: 1.28; SizeX_mm: 1.6; SizeY_mm: 0.8; SizeZ_mm: 1; EIA_Code: E192; U/M: EA; AEC Category: Q200
signal-integrity model Resistor
simulation model Resistor
footprint 0603
footprint 0603M
footprint 0603L
footprint 0603_HV
footprint 0603S
pins: 1, 2

## RT0603DRE077R06L
designator R?  ValueDisplayed: 7.06  (hidden comment: RT0603DRE077R06L)
RES, 7.06, 0.5%, 0.1 W, 0603; Manufacturer: Yageo America; CompType: Resistor; Value: 7.06; Value_Code: 7R06; Tolerance_%: 0.5; Power_W: 0.1; Value2: 0.1W; VDC_V: 75; TempCo: 50 ppm/C; SizeArea_mm2: 1.28; SizeX_mm: 1.6; SizeY_mm: 0.8; SizeZ_mm: 1; EIA_Code: E192; U/M: EA; AEC Category: Q200
signal-integrity model Resistor
simulation model Resistor
footprint 0603
footprint 0603M
footprint 0603L
footprint 0603_HV
footprint 0603S
pins: 1, 2

## RT0603DRE077R15L
designator R?  ValueDisplayed: 7.15  (hidden comment: RT0603DRE077R15L)
RES, 7.15, 0.5%, 0.1 W, 0603; Manufacturer: Yageo America; CompType: Resistor; Value: 7.15; Value_Code: 7R15; Tolerance_%: 0.5; Power_W: 0.1; Value2: 0.1W; VDC_V: 75; TempCo: 50 ppm/C; SizeArea_mm2: 1.28; SizeX_mm: 1.6; SizeY_mm: 0.8; SizeZ_mm: 1; EIA_Code: E192; U/M: EA; AEC Category: Q200
signal-integrity model Resistor
simulation model Resistor
footprint 0603
footprint 0603M
footprint 0603L
footprint 0603_HV
footprint 0603S
pins: 1, 2

## RT0603DRE077R23L
designator R?  ValueDisplayed: 7.23  (hidden comment: RT0603DRE077R23L)
RES, 7.23, 0.5%, 0.1 W, 0603; Manufacturer: Yageo America; CompType: Resistor; Value: 7.23; Value_Code: 7R23; Tolerance_%: 0.5; Power_W: 0.1; Value2: 0.1W; VDC_V: 75; TempCo: 50 ppm/C; SizeArea_mm2: 1.28; SizeX_mm: 1.6; SizeY_mm: 0.8; SizeZ_mm: 1; EIA_Code: E192; U/M: EA; AEC Category: Q200
signal-integrity model Resistor
simulation model Resistor
footprint 0603
footprint 0603M
footprint 0603L
footprint 0603_HV
footprint 0603S
pins: 1, 2

## RT0603DRE077R32L
designator R?  ValueDisplayed: 7.32  (hidden comment: RT0603DRE077R32L)
RES, 7.32, 0.5%, 0.1 W, 0603; Manufacturer: Yageo America; CompType: Resistor; Value: 7.32; Value_Code: 7R32; Tolerance_%: 0.5; Power_W: 0.1; Value2: 0.1W; VDC_V: 75; TempCo: 50 ppm/C; SizeArea_mm2: 1.28; SizeX_mm: 1.6; SizeY_mm: 0.8; SizeZ_mm: 1; EIA_Code: E192; U/M: EA; AEC Category: Q200
signal-integrity model Resistor
simulation model Resistor
footprint 0603
footprint 0603M
footprint 0603L
footprint 0603_HV
footprint 0603S
pins: 1, 2

## RT0603DRE077R41L
designator R?  ValueDisplayed: 7.41  (hidden comment: RT0603DRE077R41L)
RES, 7.41, 0.5%, 0.1 W, 0603; Manufacturer: Yageo America; CompType: Resistor; Value: 7.41; Value_Code: 7R41; Tolerance_%: 0.5; Power_W: 0.1; Value2: 0.1W; VDC_V: 75; TempCo: 50 ppm/C; SizeArea_mm2: 1.28; SizeX_mm: 1.6; SizeY_mm: 0.8; SizeZ_mm: 1; EIA_Code: E192; U/M: EA; AEC Category: Q200
signal-integrity model Resistor
simulation model Resistor
footprint 0603
footprint 0603M
footprint 0603L
footprint 0603_HV
footprint 0603S
pins: 1, 2

## RT0603DRE077R59L
designator R?  ValueDisplayed: 7.59  (hidden comment: RT0603DRE077R59L)
RES, 7.59, 0.5%, 0.1 W, 0603; Manufacturer: Yageo America; CompType: Resistor; Value: 7.59; Value_Code: 7R59; Tolerance_%: 0.5; Power_W: 0.1; Value2: 0.1W; VDC_V: 75; TempCo: 50 ppm/C; SizeArea_mm2: 1.28; SizeX_mm: 1.6; SizeY_mm: 0.8; SizeZ_mm: 1; EIA_Code: E192; U/M: EA; AEC Category: Q200
signal-integrity model Resistor
simulation model Resistor
footprint 0603
footprint 0603M
footprint 0603L
footprint 0603_HV
footprint 0603S
pins: 1, 2

## RT0603DRE077R68L
designator R?  ValueDisplayed: 7.68  (hidden comment: RT0603DRE077R68L)
RES, 7.68, 0.5%, 0.1 W, 0603; Manufacturer: Yageo America; CompType: Resistor; Value: 7.68; Value_Code: 7R68; Tolerance_%: 0.5; Power_W: 0.1; Value2: 0.1W; VDC_V: 75; TempCo: 50 ppm/C; SizeArea_mm2: 1.28; SizeX_mm: 1.6; SizeY_mm: 0.8; SizeZ_mm: 1; EIA_Code: E192; U/M: EA; AEC Category: Q200
signal-integrity model Resistor
simulation model Resistor
footprint 0603
footprint 0603M
footprint 0603L
footprint 0603_HV
footprint 0603S
pins: 1, 2

## RT0603DRE077R77L
designator R?  ValueDisplayed: 7.77  (hidden comment: RT0603DRE077R77L)
RES, 7.77, 0.5%, 0.1 W, 0603; Manufacturer: Yageo America; CompType: Resistor; Value: 7.77; Value_Code: 7R77; Tolerance_%: 0.5; Power_W: 0.1; Value2: 0.1W; VDC_V: 75; TempCo: 50 ppm/C; SizeArea_mm2: 1.28; SizeX_mm: 1.6; SizeY_mm: 0.8; SizeZ_mm: 1; EIA_Code: E192; U/M: EA; AEC Category: Q200
signal-integrity model Resistor
simulation model Resistor
footprint 0603
footprint 0603M
footprint 0603L
footprint 0603_HV
footprint 0603S
pins: 1, 2

## RT0603DRE077R87L
designator R?  ValueDisplayed: 7.87  (hidden comment: RT0603DRE077R87L)
RES, 7.87, 0.5%, 0.1 W, 0603; Manufacturer: Yageo America; CompType: Resistor; Value: 7.87; Value_Code: 7R87; Tolerance_%: 0.5; Power_W: 0.1; Value2: 0.1W; VDC_V: 75; TempCo: 50 ppm/C; SizeArea_mm2: 1.28; SizeX_mm: 1.6; SizeY_mm: 0.8; SizeZ_mm: 1; EIA_Code: E192; U/M: EA; AEC Category: Q200
signal-integrity model Resistor
simulation model Resistor
footprint 0603
footprint 0603M
footprint 0603L
footprint 0603_HV
footprint 0603S
pins: 1, 2

## RT0603DRE077R96L
designator R?  ValueDisplayed: 7.96  (hidden comment: RT0603DRE077R96L)
RES, 7.96, 0.5%, 0.1 W, 0603; Manufacturer: Yageo America; CompType: Resistor; Value: 7.96; Value_Code: 7R96; Tolerance_%: 0.5; Power_W: 0.1; Value2: 0.1W; VDC_V: 75; TempCo: 50 ppm/C; SizeArea_mm2: 1.28; SizeX_mm: 1.6; SizeY_mm: 0.8; SizeZ_mm: 1; EIA_Code: E192; U/M: EA; AEC Category: Q200
signal-integrity model Resistor
simulation model Resistor
footprint 0603
footprint 0603M
footprint 0603L
footprint 0603_HV
footprint 0603S
pins: 1, 2

## RT0603DRE078K06L
designator R?  ValueDisplayed: 8.06k  (hidden comment: RT0603DRE078K06L)
RES, 8.06 k, 0.5%, 0.1 W, 0603; Manufacturer: Yageo America; CompType: Resistor; Value: 8.06k; Res_ohm: 8060; Value_Code: 8k06; Tolerance_%: 0.5; Power_W: 0.1; Value2: 0.1W; VDC_V: 75; TempCo: 50 ppm/C; SizeArea_mm2: 1.28; SizeX_mm: 1.6; SizeY_mm: 0.8; SizeZ_mm: 1; EIA_Code: E192; U/M: EA; AEC Category: Q200
signal-integrity model Resistor
simulation model Resistor
footprint 0603
footprint 0603M
footprint 0603L
footprint 0603_HV
footprint 0603S
pins: 1, 2

## RT0603DRE078K16L
designator R?  ValueDisplayed: 8.16k  (hidden comment: RT0603DRE078K16L)
RES, 8.16 k, 0.5%, 0.1 W, 0603; Manufacturer: Yageo America; CompType: Resistor; Value: 8.16k; Res_ohm: 8160; Value_Code: 8k16; Tolerance_%: 0.5; Power_W: 0.1; Value2: 0.1W; VDC_V: 75; TempCo: 50 ppm/C; SizeArea_mm2: 1.28; SizeX_mm: 1.6; SizeY_mm: 0.8; SizeZ_mm: 1; EIA_Code: E192; U/M: EA; AEC Category: Q200
signal-integrity model Resistor
simulation model Resistor
footprint 0603
footprint 0603M
footprint 0603L
footprint 0603_HV
footprint 0603S
pins: 1, 2

## RT0603DRE078K25L
designator R?  ValueDisplayed: 8.25k  (hidden comment: RT0603DRE078K25L)
RES, 8.25 k, 0.5%, 0.1 W, 0603; Manufacturer: Yageo America; CompType: Resistor; Value: 8.25k; Res_ohm: 8250; Value_Code: 8k25; Tolerance_%: 0.5; Power_W: 0.1; Value2: 0.1W; VDC_V: 75; TempCo: 50 ppm/C; SizeArea_mm2: 1.28; SizeX_mm: 1.6; SizeY_mm: 0.8; SizeZ_mm: 1; EIA_Code: E192; U/M: EA; AEC Category: Q200
signal-integrity model Resistor
simulation model Resistor
footprint 0603
footprint 0603M
footprint 0603L
footprint 0603_HV
footprint 0603S
pins: 1, 2

## RT0603DRE078K35L
designator R?  ValueDisplayed: 8.35k  (hidden comment: RT0603DRE078K35L)
RES, 8.35 k, 0.5%, 0.1 W, 0603; Manufacturer: Yageo America; CompType: Resistor; Value: 8.35k; Res_ohm: 8350; Value_Code: 8k35; Tolerance_%: 0.5; Power_W: 0.1; Value2: 0.1W; VDC_V: 75; TempCo: 50 ppm/C; SizeArea_mm2: 1.28; SizeX_mm: 1.6; SizeY_mm: 0.8; SizeZ_mm: 1; EIA_Code: E192; U/M: EA; AEC Category: Q200
signal-integrity model Resistor
simulation model Resistor
footprint 0603
footprint 0603M
footprint 0603L
footprint 0603_HV
footprint 0603S
pins: 1, 2

## RT0603DRE078K45L
designator R?  ValueDisplayed: 8.45k  (hidden comment: RT0603DRE078K45L)
RES, 8.45 k, 0.5%, 0.1 W, 0603; Manufacturer: Yageo America; CompType: Resistor; Value: 8.45k; Res_ohm: 8450; Value_Code: 8k45; Tolerance_%: 0.5; Power_W: 0.1; Value2: 0.1W; VDC_V: 75; TempCo: 50 ppm/C; SizeArea_mm2: 1.28; SizeX_mm: 1.6; SizeY_mm: 0.8; SizeZ_mm: 1; EIA_Code: E192; U/M: EA; AEC Category: Q200
signal-integrity model Resistor
simulation model Resistor
footprint 0603
footprint 0603M
footprint 0603L
footprint 0603_HV
footprint 0603S
pins: 1, 2

## RT0603DRE078K56L
designator R?  ValueDisplayed: 8.56k  (hidden comment: RT0603DRE078K56L)
RES, 8.56 k, 0.5%, 0.1 W, 0603; Manufacturer: Yageo America; CompType: Resistor; Value: 8.56k; Res_ohm: 8560; Value_Code: 8k56; Tolerance_%: 0.5; Power_W: 0.1; Value2: 0.1W; VDC_V: 75; TempCo: 50 ppm/C; SizeArea_mm2: 1.28; SizeX_mm: 1.6; SizeY_mm: 0.8; SizeZ_mm: 1; EIA_Code: E192; U/M: EA; AEC Category: Q200
signal-integrity model Resistor
simulation model Resistor
footprint 0603
footprint 0603M
footprint 0603L
footprint 0603_HV
footprint 0603S
pins: 1, 2

## RT0603DRE078K66L
designator R?  ValueDisplayed: 8.66k  (hidden comment: RT0603DRE078K66L)
RES, 8.66 k, 0.5%, 0.1 W, 0603; Manufacturer: Yageo America; CompType: Resistor; Value: 8.66k; Res_ohm: 8660; Value_Code: 8k66; Tolerance_%: 0.5; Power_W: 0.1; Value2: 0.1W; VDC_V: 75; TempCo: 50 ppm/C; SizeArea_mm2: 1.28; SizeX_mm: 1.6; SizeY_mm: 0.8; SizeZ_mm: 1; EIA_Code: E192; U/M: EA; AEC Category: Q200
signal-integrity model Resistor
simulation model Resistor
footprint 0603
footprint 0603M
footprint 0603L
footprint 0603_HV
footprint 0603S
pins: 1, 2

## RT0603DRE078K76L
designator R?  ValueDisplayed: 8.76k  (hidden comment: RT0603DRE078K76L)
RES, 8.76 k, 0.5%, 0.1 W, 0603; Manufacturer: Yageo America; CompType: Resistor; Value: 8.76k; Res_ohm: 8760; Value_Code: 8k76; Tolerance_%: 0.5; Power_W: 0.1; Value2: 0.1W; VDC_V: 75; TempCo: 50 ppm/C; SizeArea_mm2: 1.28; SizeX_mm: 1.6; SizeY_mm: 0.8; SizeZ_mm: 1; EIA_Code: E192; U/M: EA; AEC Category: Q200
signal-integrity model Resistor
simulation model Resistor
footprint 0603
footprint 0603M
footprint 0603L
footprint 0603_HV
footprint 0603S
pins: 1, 2

## RT0603DRE078K87L
designator R?  ValueDisplayed: 8.87k  (hidden comment: RT0603DRE078K87L)
RES, 8.87 k, 0.5%, 0.1 W, 0603; Manufacturer: Yageo America; CompType: Resistor; Value: 8.87k; Res_ohm: 8870; Value_Code: 8k87; Tolerance_%: 0.5; Power_W: 0.1; Value2: 0.1W; VDC_V: 75; TempCo: 50 ppm/C; SizeArea_mm2: 1.28; SizeX_mm: 1.6; SizeY_mm: 0.8; SizeZ_mm: 1; EIA_Code: E192; U/M: EA; AEC Category: Q200
signal-integrity model Resistor
simulation model Resistor
footprint 0603
footprint 0603M
footprint 0603L
footprint 0603_HV
footprint 0603S
pins: 1, 2

## RT0603DRE078K98L
designator R?  ValueDisplayed: 8.98k  (hidden comment: RT0603DRE078K98L)
RES, 8.98 k, 0.5%, 0.1 W, 0603; Manufacturer: Yageo America; CompType: Resistor; Value: 8.98k; Res_ohm: 8980; Value_Code: 8k98; Tolerance_%: 0.5; Power_W: 0.1; Value2: 0.1W; VDC_V: 75; TempCo: 50 ppm/C; SizeArea_mm2: 1.28; SizeX_mm: 1.6; SizeY_mm: 0.8; SizeZ_mm: 1; EIA_Code: E192; U/M: EA; AEC Category: Q200
signal-integrity model Resistor
simulation model Resistor
footprint 0603
footprint 0603M
footprint 0603L
footprint 0603_HV
footprint 0603S
pins: 1, 2

## RT0603DRE078R06L
designator R?  ValueDisplayed: 8.06  (hidden comment: RT0603DRE078R06L)
RES, 8.06, 0.5%, 0.1 W, 0603; Manufacturer: Yageo America; CompType: Resistor; Value: 8.06; Value_Code: 8R06; Tolerance_%: 0.5; Power_W: 0.1; Value2: 0.1W; VDC_V: 75; TempCo: 50 ppm/C; SizeArea_mm2: 1.28; SizeX_mm: 1.6; SizeY_mm: 0.8; SizeZ_mm: 1; EIA_Code: E192; U/M: EA; AEC Category: Q200
signal-integrity model Resistor
simulation model Resistor
footprint 0603
footprint 0603M
footprint 0603L
footprint 0603_HV
footprint 0603S
pins: 1, 2

## RT0603DRE078R16L
designator R?  ValueDisplayed: 8.16  (hidden comment: RT0603DRE078R16L)
RES, 8.16, 0.5%, 0.1 W, 0603; Manufacturer: Yageo America; CompType: Resistor; Value: 8.16; Value_Code: 8R16; Tolerance_%: 0.5; Power_W: 0.1; Value2: 0.1W; VDC_V: 75; TempCo: 50 ppm/C; SizeArea_mm2: 1.28; SizeX_mm: 1.6; SizeY_mm: 0.8; SizeZ_mm: 1; EIA_Code: E192; U/M: EA; AEC Category: Q200
signal-integrity model Resistor
simulation model Resistor
footprint 0603
footprint 0603M
footprint 0603L
footprint 0603_HV
footprint 0603S
pins: 1, 2

## RT0603DRE078R25L
designator R?  ValueDisplayed: 8.25  (hidden comment: RT0603DRE078R25L)
RES, 8.25, 0.5%, 0.1 W, 0603; Manufacturer: Yageo America; CompType: Resistor; Value: 8.25; Value_Code: 8R25; Tolerance_%: 0.5; Power_W: 0.1; Value2: 0.1W; VDC_V: 75; TempCo: 50 ppm/C; SizeArea_mm2: 1.28; SizeX_mm: 1.6; SizeY_mm: 0.8; SizeZ_mm: 1; EIA_Code: E192; U/M: EA; AEC Category: Q200
signal-integrity model Resistor
simulation model Resistor
footprint 0603
footprint 0603M
footprint 0603L
footprint 0603_HV
footprint 0603S
pins: 1, 2

## RT0603DRE078R35L
designator R?  ValueDisplayed: 8.35  (hidden comment: RT0603DRE078R35L)
RES, 8.35, 0.5%, 0.1 W, 0603; Manufacturer: Yageo America; CompType: Resistor; Value: 8.35; Value_Code: 8R35; Tolerance_%: 0.5; Power_W: 0.1; Value2: 0.1W; VDC_V: 75; TempCo: 50 ppm/C; SizeArea_mm2: 1.28; SizeX_mm: 1.6; SizeY_mm: 0.8; SizeZ_mm: 1; EIA_Code: E192; U/M: EA; AEC Category: Q200
signal-integrity model Resistor
simulation model Resistor
footprint 0603
footprint 0603M
footprint 0603L
footprint 0603_HV
footprint 0603S
pins: 1, 2

## RT0603DRE078R45L
designator R?  ValueDisplayed: 8.45  (hidden comment: RT0603DRE078R45L)
RES, 8.45, 0.5%, 0.1 W, 0603; Manufacturer: Yageo America; CompType: Resistor; Value: 8.45; Value_Code: 8R45; Tolerance_%: 0.5; Power_W: 0.1; Value2: 0.1W; VDC_V: 75; TempCo: 50 ppm/C; SizeArea_mm2: 1.28; SizeX_mm: 1.6; SizeY_mm: 0.8; SizeZ_mm: 1; EIA_Code: E192; U/M: EA; AEC Category: Q200
signal-integrity model Resistor
simulation model Resistor
footprint 0603
footprint 0603M
footprint 0603L
footprint 0603_HV
footprint 0603S
pins: 1, 2

## RT0603DRE078R56L
designator R?  ValueDisplayed: 8.56  (hidden comment: RT0603DRE078R56L)
RES, 8.56, 0.5%, 0.1 W, 0603; Manufacturer: Yageo America; CompType: Resistor; Value: 8.56; Value_Code: 8R56; Tolerance_%: 0.5; Power_W: 0.1; Value2: 0.1W; VDC_V: 75; TempCo: 50 ppm/C; SizeArea_mm2: 1.28; SizeX_mm: 1.6; SizeY_mm: 0.8; SizeZ_mm: 1; EIA_Code: E192; U/M: EA; AEC Category: Q200
signal-integrity model Resistor
simulation model Resistor
footprint 0603
footprint 0603M
footprint 0603L
footprint 0603_HV
footprint 0603S
pins: 1, 2

## RT0603DRE078R66L
designator R?  ValueDisplayed: 8.66  (hidden comment: RT0603DRE078R66L)
RES, 8.66, 0.5%, 0.1 W, 0603; Manufacturer: Yageo America; CompType: Resistor; Value: 8.66; Value_Code: 8R66; Tolerance_%: 0.5; Power_W: 0.1; Value2: 0.1W; VDC_V: 75; TempCo: 50 ppm/C; SizeArea_mm2: 1.28; SizeX_mm: 1.6; SizeY_mm: 0.8; SizeZ_mm: 1; EIA_Code: E192; U/M: EA; AEC Category: Q200
signal-integrity model Resistor
simulation model Resistor
footprint 0603
footprint 0603M
footprint 0603L
footprint 0603_HV
footprint 0603S
pins: 1, 2

## RT0603DRE078R76L
designator R?  ValueDisplayed: 8.76  (hidden comment: RT0603DRE078R76L)
RES, 8.76, 0.5%, 0.1 W, 0603; Manufacturer: Yageo America; CompType: Resistor; Value: 8.76; Value_Code: 8R76; Tolerance_%: 0.5; Power_W: 0.1; Value2: 0.1W; VDC_V: 75; TempCo: 50 ppm/C; SizeArea_mm2: 1.28; SizeX_mm: 1.6; SizeY_mm: 0.8; SizeZ_mm: 1; EIA_Code: E192; U/M: EA; AEC Category: Q200
signal-integrity model Resistor
simulation model Resistor
footprint 0603
footprint 0603M
footprint 0603L
footprint 0603_HV
footprint 0603S
pins: 1, 2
